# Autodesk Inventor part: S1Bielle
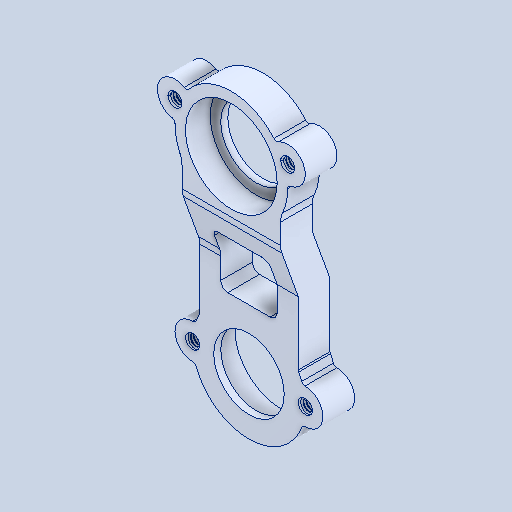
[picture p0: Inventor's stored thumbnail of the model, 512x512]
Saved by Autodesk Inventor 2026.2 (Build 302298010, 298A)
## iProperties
Created: 1601-01
Part Number: S1Bielle
Material: 1060 Alloy
Document SubType Name: Modeling
Designer: mel
Density: 2.7 g/cm^3
Appearance: satin finish aluminum
Author: mel
Sending System: SOLIDWORKS 2023
Part Number: Bielle
Last Saved Date: 2025-04-02
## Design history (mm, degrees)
feature "Filetage4"
node "Plan1"
node "Plan2"
node "Plan3"
node "Plan4"
node "Solide1"
